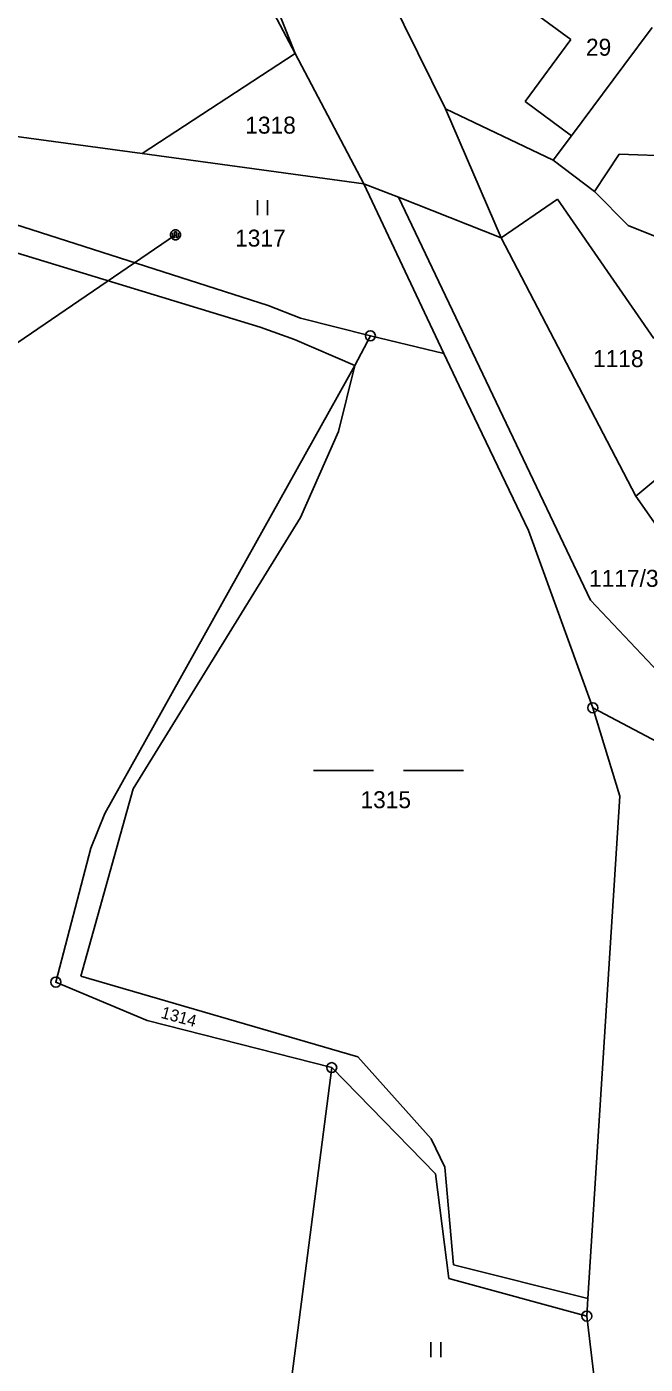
# Model space of a CAD drawing. Extents: x -796130 to -793145, y -1109506 to -1106267.
# Drawn here: x -794504.5 to -794442.6, y -1107964 to -1107830.1 of the extents above; entities that cross this region are included whole.
import ezdxf

# ---------------------------------------------------------------- set-up
doc = ezdxf.new("R2010")
doc.units = 0
for name, color, linetype in [('Vrstva 1', 7, 'Continuous'), ('Vrstva 12', 7, 'Continuous'), ('Vrstva 14', 7, 'Continuous'), ('Vrstva 15', 7, 'Continuous'), ('Vrstva 16', 7, 'Continuous'), ('Vrstva 2', 7, 'Continuous'), ('Vrstva 23', 7, 'Continuous'), ('Vrstva 26', 7, 'Continuous'), ('Vrstva 28', 7, 'Continuous')]:
    doc.layers.add(name, color=color, linetype=linetype)

msp = doc.modelspace()

# ---------------------------------------------------------------- linework, layer by layer
at = {"layer": 'Vrstva 1'}
for p, q in [((-794477.65, -1107832.78), (-794488.44, -1107805.91)), ((-794485.37, -1107818.12), (-794477.65, -1107832.78)), ((-794470, -1107823.36), (-794462.61, -1107838.31)), ((-794441.95, -1107830.18), (-794444.77, -1107833.97)), ((-794492.95, -1107842.79), (-794477.65, -1107832.78)), ((-794477.65, -1107832.78), (-794470.77, -1107845.81)), ((-794444.77, -1107833.97), (-794450.01, -1107841.01)), ((-794451.84, -1107843.46), (-794462.61, -1107838.31)), ((-794462.61, -1107838.31), (-794457.03, -1107851.22)), ((-794519.09, -1107839.24), (-794492.95, -1107842.79)), ((-794450.01, -1107841.01), (-794451.84, -1107843.46)), ((-794480.34, -1107858.02), (-794528.05, -1107842.7)), ((-794492.95, -1107842.79), (-794470.77, -1107845.81)), ((-794451.84, -1107843.46), (-794447.72, -1107846.59)), ((-794447.72, -1107846.59), (-794445.24, -1107842.84)), ((-794445.24, -1107842.84), (-794432.79, -1107843.3)), ((-794528.03, -1107845.84), (-794481.15, -1107860.19)), ((-794470.77, -1107845.81), (-794467.31, -1107847.17)), ((-794462.78, -1107862.8), (-794470.77, -1107845.81)), ((-794467.31, -1107847.17), (-794457.03, -1107851.22)), ((-794457.03, -1107851.22), (-794451.41, -1107847.35)), ((-794451.41, -1107847.35), (-794441.76, -1107861.32)), ((-794447.72, -1107846.59), (-794444.34, -1107850)), ((-794444.34, -1107850), (-794423.33, -1107858.45)), ((-794457.03, -1107851.22), (-794443.59, -1107877.11)), ((-794477.12, -1107859.28), (-794480.34, -1107858.02)), ((-794470.13, -1107861.04), (-794477.12, -1107859.28)), ((-794481.15, -1107860.19), (-794477.73, -1107861.4)), ((-794471.67, -1107864.02), (-794470.13, -1107861.04)), ((-794470.13, -1107861.04), (-794462.78, -1107862.8)), ((-794477.73, -1107861.4), (-794471.67, -1107864.02)), ((-794461.25, -1107866.05), (-794462.78, -1107862.8)), ((-794496.68, -1107908.85), (-794471.67, -1107864.02)), ((-794471.67, -1107864.02), (-794473.32, -1107870.63)), ((-794461.25, -1107866.05), (-794454.32, -1107880.53)), ((-794434.61, -1107869.56), (-794443.59, -1107877.11)), ((-794473.32, -1107870.63), (-794477.12, -1107879.24)), ((-794443.59, -1107877.11), (-794441.54, -1107880)), ((-794477.12, -1107879.24), (-794493.86, -1107906.38)), ((-794454.32, -1107880.53), (-794447.88, -1107898.28)), ((-794447.88, -1107898.28), (-794403.89, -1107921.59)), ((-794447.88, -1107898.28), (-794445.17, -1107907.12)), ((-794493.86, -1107906.38), (-794499.1, -1107925.13)), ((-794445.17, -1107907.12), (-794448.37, -1107957.43)), ((-794498.1, -1107912.33), (-794496.68, -1107908.85)), ((-794501.59, -1107925.74), (-794498.1, -1107912.33)), ((-794499.1, -1107925.13), (-794471.39, -1107933.22)), ((-794492.44, -1107929.58), (-794501.59, -1107925.74)), ((-794474, -1107934.3), (-794492.44, -1107929.58)), ((-794471.39, -1107933.22), (-794464.06, -1107941.44)), ((-794479.59, -1107977.8), (-794474, -1107934.3)), ((-794463.62, -1107944.92), (-794474, -1107934.3)), ((-794464.06, -1107941.44), (-794462.67, -1107944.26)), ((-794463.62, -1107944.92), (-794462.27, -1107955.4)), ((-794462.67, -1107944.26), (-794461.81, -1107954.06)), ((-794461.81, -1107954.06), (-794448.37, -1107957.43)), ((-794448.48, -1107959.18), (-794462.27, -1107955.4)), ((-794448.37, -1107957.43), (-794448.48, -1107959.18)), ((-794448.48, -1107959.18), (-794446.64, -1107974.51))]:
    msp.add_line(p, q, dxfattribs=at)
at = {"layer": 'Vrstva 12'}
msp.add_line((-794546.81, -1107889.98), (-794489.62, -1107850.92), dxfattribs=at)
at = {"layer": 'Vrstva 2'}
for p, q in [((-794450.08, -1107831.37), (-794456.22, -1107826.85)), ((-794454.66, -1107837.58), (-794450.08, -1107831.37)), ((-794454.66, -1107837.58), (-794450.01, -1107841.01)), ((-794467.31, -1107847.17), (-794448.11, -1107887.49)), ((-794448.11, -1107887.49), (-794437.37, -1107898.89))]:
    msp.add_line(p, q, dxfattribs=at)
at = {"layer": 'Vrstva 23'}
for p, q in [((-794481.42, -1107848.97), (-794481.42, -1107847.47)), ((-794480.42, -1107847.47), (-794480.42, -1107848.97)), ((-794475.82, -1107904.57), (-794469.82, -1107904.57)), ((-794466.82, -1107904.57), (-794460.82, -1107904.57)), ((-794464.08, -1107963.28), (-794464.08, -1107961.78)), ((-794463.08, -1107961.78), (-794463.08, -1107963.28))]:
    msp.add_line(p, q, dxfattribs=at)
at = {"layer": 'Vrstva 26'}
for p, q in [((-794489.92, -1107850.52), (-794489.72, -1107850.42)), ((-794489.72, -1107850.42), (-794489.52, -1107850.42)), ((-794489.52, -1107850.42), (-794489.32, -1107850.52)), ((-794490.12, -1107850.82), (-794490.02, -1107850.62)), ((-794490.12, -1107851.02), (-794490.12, -1107850.82)), ((-794490.02, -1107851.22), (-794490.12, -1107851.02)), ((-794490.02, -1107850.62), (-794489.92, -1107850.52)), ((-794489.92, -1107851.32), (-794490.02, -1107851.22)), ((-794489.92, -1107850.72), (-794489.92, -1107851.12)), ((-794489.92, -1107851.12), (-794489.72, -1107851.22)), ((-794489.72, -1107851.42), (-794489.92, -1107851.32)), ((-794489.72, -1107851.22), (-794489.72, -1107850.62)), ((-794489.72, -1107850.62), (-794489.52, -1107850.62)), ((-794489.52, -1107851.42), (-794489.72, -1107851.42)), ((-794489.52, -1107850.62), (-794489.52, -1107851.22)), ((-794489.52, -1107851.22), (-794489.32, -1107851.12)), ((-794489.32, -1107851.32), (-794489.52, -1107851.42)), ((-794489.32, -1107850.52), (-794489.22, -1107850.62)), ((-794489.32, -1107851.12), (-794489.32, -1107850.72)), ((-794489.22, -1107851.22), (-794489.32, -1107851.32)), ((-794489.22, -1107850.62), (-794489.12, -1107850.82)), ((-794489.12, -1107851.02), (-794489.22, -1107851.22)), ((-794489.12, -1107850.82), (-794489.12, -1107851.02))]:
    msp.add_line(p, q, dxfattribs=at)
at = {"layer": 'Vrstva 28'}
for centre, radius in [((-794470.13, -1107861.04), 0.5), ((-794470.13, -1107861.04), 0.01), ((-794447.88, -1107898.28), 0.5), ((-794447.88, -1107898.28), 0.01), ((-794501.59, -1107925.74), 0.5), ((-794501.59, -1107925.74), 0.01), ((-794474, -1107934.3), 0.5), ((-794474, -1107934.3), 0.01), ((-794448.48, -1107959.18), 0.5), ((-794448.48, -1107959.18), 0.01)]:
    msp.add_circle(centre, radius, dxfattribs=at)

# ---------------------------------------------------------------- texts
at = {"layer": 'Vrstva 14'}
for s, p in [('1318', (-794482.643, -1107840.8)), ('1317', (-794483.66, -1107852.11)), ('1118', (-794447.856, -1107864.17)), ('1315', (-794471.119, -1107908.33))]:
    msp.add_text(s, height=1.7, dxfattribs=at).set_placement(p)
msp.add_text('1314', height=1.2, rotation=344.7, dxfattribs=at).set_placement((-794491.156, -1107929.306))
at = {"layer": 'Vrstva 15'}
msp.add_text('29', height=1.7, dxfattribs=at).set_placement((-794448.56, -1107833))
at = {"layer": 'Vrstva 16'}
msp.add_text('1117/3', height=1.7, dxfattribs=at).set_placement((-794448.256, -1107886.17))

doc.saveas('drawing.dxf')
